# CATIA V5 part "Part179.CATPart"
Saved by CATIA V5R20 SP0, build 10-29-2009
Part number: FA 126700-1
Revision: ANY
Definition: UNKNOWN
Nomenclature: FA 126700-1
Source: Unknown
Bounding box of the stored display mesh (mm): x -3.804 to 3.804, y 0.2 to 2.5, z -4 to 4
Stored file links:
  C:\Users\Utente\Desktop\IO LAVORO\3D X SITO CF\CUMSA\3D files FA\FA 126712-20\Part179.CATPart

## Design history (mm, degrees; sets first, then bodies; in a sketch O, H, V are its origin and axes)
Body1 "Cortar-Extruir1" (main body)
  Solid1: solid without history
